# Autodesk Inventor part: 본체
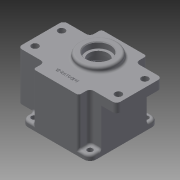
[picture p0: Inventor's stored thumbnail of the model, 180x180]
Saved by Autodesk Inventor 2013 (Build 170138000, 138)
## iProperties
Created: 2015-07
Part Number: 본체
Material: 일반
Document SubType Name: Modeling
Designer: user
Density: 1 g/cm^3
Author: user
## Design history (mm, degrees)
sketch "스케치1"
  geometry: L1 (65, 30)-(65, -30); L2 (-65, -30)-(-65, 30); L3 (-30, 45)-(30, 45); L4 (30, -45)-(-30, -45); L5 (30, 45)-(30, 30); L6 (30, -30)-(30, -45); L7 (-65, 30)-(-30, 30); L8 (30, 30)-(65, 30); L9 (-30, -45)-(-30, -30); L10 (-30, 30)-(-30, 45); L11 (65, -30)-(30, -30); L12 (-30, -30)-(-65, -30); 4 further points
  constraints: 24 end point, 10 parallel, 4 perpendicular, 3 horizontal, 2 horizontal alignment, 2 midpoint, 1 vertical alignment
  dimensions: "d0" = 130 distance of L1.end L2.start; "d1" = 60 distance of L1.start L1.end; "d3" = 60 distance of L4.start L4.end; "d4" = 90 distance of L3.end L4.start
extrude "돌출1" new body sketch "스케치1" distance "d5" = 12; taper "d6" = 0 deg
sketch "스케치2"
  geometry: L1 (-9047.762, 104.614)-(-9047.762, 74.603); L2 (30, 45)-(-30, 45); L3 (-45, 30)-(-45, -30); L4 (-30, -45)-(30, -45); L5 (45, -30)-(45, 30); L6 (30, -45)-(0, -45); L7 (45, 0)-(45, -30); L8 (28.924, 45)-(0, 45); L9 (30, 30)-(65, 30) reference; L10 (65, 30)-(65, -30) reference; L11 (65, -30)-(30, -30) reference; L12 (30, -30)-(30, -45) reference; L13 (30, -45)-(-30, -45) reference; L14 (-30, -45)-(-30, -30) reference; L15 (-30, -30)-(-65, -30) reference; L16 (-65, -30)-(-65, 30) reference; L17 (-65, 30)-(-30, 30) reference; L18 (-30, 30)-(-30, 45) reference; L19 (-30, 45)-(30, 45) reference; L20 (30, 45)-(30, 30) reference; L21 (-30, 45)-(-30, 30); L22 (-30, 30)-(-45, 30); L23 (30, 30)-(45, 30); L24 (30, 45)-(30, 30); L25 (30, -30)-(45, -30); L26 (30, -45)-(30, -30); L27 (-30, -30)-(-45, -30); L28 (-30, -45)-(-30, -30); 1 further point
  constraints: 32 end point, 6 horizontal, 4 parallel, 2 point on line, 1 perpendicular
  dimensions: "d103" = 90 deg angle of L10 L22; "d104" = 90 deg angle of L9 L26; "d105" = 90 deg angle of L9 L21; "d106" = 90 deg angle of L9 L28; "d107" = 20 distance between parallel lines of L10 L5; "d108" = 110 distance between parallel lines of L10 L3; "d109" = 9112.76236 distance between parallel lines of L10 L1; "d110" = 75 distance between parallel lines of L9 L6; "d111" = 15 distance between parallel lines of L9 L2; "d112" = 90 distance between parallel lines of L13 L8; "d113" = 30 distance from line of L7.start L11; "d114" = 36.07569 distance from line of L8.start L10; "d115" = 65 distance from line of L8.end L10; "d116" = 65 distance from line of L6.end L10; "d117" = 134.61417 distance from line of L1.start L11; "d118" = 104.60322 distance from line of L1.end L11
extrude "돌출2" join sketch "스케치2" distance "d14" = 51; taper "d15" = 0 deg
sketch "스케치3"
  geometry: L1 (-45, -45)-(45, -45); L2 (45, -45)-(45, 45); L3 (45, 45)-(-45, 45); L4 (-45, 45)-(-45, -45); 1 further point
  constraints: 8 end point, 2 parallel, 1 horizontal, 1 perpendicular
extrude "돌출3" join sketch "스케치3" distance "d16" = 7; taper "d17" = 0 deg
fillet "모깎기2" dims "d18" = 8
sketch "스케치4"
  geometry: L1 (-37, 45)-(-30, 45) reference; L2 (45, 37)-(45, 30) reference; L3 (37, -45)-(30, -45) reference; L4 (-45, -37)-(-45, -30) reference; L5 (-45, 30)-(-30, 30) reference; L6 (30, 30)-(45, 30) reference; L7 (45, -30)-(30, -30) reference; L8 (-30, -30)-(-45, -30) reference; L9 (-30, -45)-(-37, -45) reference; L10 (30, 45)-(37, 45) reference; L11 (30, 45)-(30, 30) reference; L12 (-30, 45)-(30, 45) reference; L13 (-30, 30)-(-30, 45) reference; L14 (-45, -30)-(-45, 30) reference; L15 (-45, -30)-(-65, -30) reference; L16 (-65, -30)-(-65, 30) reference; L17 (-65, 30)-(-45, 30) reference; L18 (-45, 30)-(-45, 37) reference; L19 (45, 30)-(45, -30) reference; L20 (65, -30)-(45, -30) reference; L21 (65, 30)-(65, -30) reference; L22 (45, 30)-(65, 30) reference; L23 (-30, -45)-(-30, -30) reference; L24 (30, -45)-(-30, -45) reference; L25 (30, -30)-(30, -45) reference; L26 (45, -30)-(45, -37) reference; C1 r 3.5 at (37, 37); C2 r 3.5 at (-37, 37); C3 r 3.5 at (-37, -37); C4 r 3.5 at (37, -37); A1 r 8 centre (-37, 37) between (-37, 45) and (-45, 37) reference; A2 r 8 centre (37, 37) between (45, 37) and (37, 45) reference; A3 r 8 centre (37, -37) between (37, -45) and (45, -37) reference; A4 r 8 centre (-37, -37) between (-45, -37) and (-37, -45) reference; 1 further point
  constraints: 4 centre point, 4 coincident
  dimensions: "d19" = 3.5 radius of C1; "d20" = 3.5 radius of C2; "d21" = 3.5 radius of C3; "d22" = 3.5 radius of C4
extrude "돌출4" cut sketch "스케치4" distance "d23" = 7; taper "d24" = 0 deg
sketch "스케치5"
  geometry: L1 (65, -30)-(65, 30) reference; L2 (-55, 17.5)-(55, 17.5); L3 (55, 17.5)-(55, -17.5); L4 (55, -17.5)-(-55, -17.5); L5 (-55, -17.5)-(-55, 17.5); C1 r 4.5 at (-55, 17.5); C2 r 4.5 at (-55, -17.5); C3 r 4.5 at (55, -17.5); C4 r 4.5 at (55, 17.5); 6 further points
  constraints: 8 end point, 4 centre point, 4 coincident, 3 midpoint, 2 parallel, 1 horizontal, 1 horizontal alignment, 1 perpendicular, 1 vertical alignment
  dimensions: "d25" = 110 distance of L3.end L4.end; "d26" = 35 distance of L2.end L3.end; "d27" = 4.5 radius of C1; "d28" = 4.5 radius of C2; "d29" = 4.5 radius of C3; "d30" = 4.5 radius of C4
extrude "돌출5" cut sketch "스케치5" distance "d31" = 20; taper "d32" = 0 deg
sketch "스케치6"
  geometry: C1 r 40 at (0, 0); 1 further point
  constraints: 1 centre point, 1 coincident
  dimensions: "d33" = 40 radius of C1
extrude "돌출6" cut sketch "스케치6" distance "d34" = 9; taper "d35" = 0 deg
sketch "스케치7"
  geometry: C1 r 40 at (0, 0) reference; C2 r 39 at (0, 0)
  constraints: 1 centre point, 1 coincident
  dimensions: "d36" = 39 radius of C2
extrude "돌출7" cut sketch "스케치7" distance "d38" = 52; taper "d39" = 0 deg
sketch "스케치14"
  geometry: L1 (45, -37)-(45, 37) reference; L2 (0, 0)-(44.326, 0); L3 (0, 0)-(-24.749, 24.749); L4 (0, 0)-(-24.749, -24.749); L5 (0, 0)-(24.749, -24.749); L6 (0, 0)-(24.749, 24.749); A1 r 40 centre (0, 0) between (-21.902, 33.471) and (-33.471, 21.902) reference; A2 r 35 centre (0, 0) between (-24.749, 24.749) and (-21.678, 27.478); A3 r 4 centre (-24.749, 24.749) between (-27.839, 22.208) and (-22.208, 27.839); A4 r 3.5 centre (-19.986, 30.542) between (-21.902, 33.471) and (-21.678, 27.478); A5 r 3.5 centre (-30.542, 19.986) between (-27.478, 21.678) and (-33.471, 21.902)
  constraints: 13 point on circle, 10 end point, 4 centre point, 4 tangent, 2 coincident, 1 horizontal, 13 other
  dimensions: "d56" = 35 radius of A2; "d60" = 360 deg dimension on A1.centre L3.end (derived); "d62" = 4 radius of A3; "d63" = 3.5 radius of A4; "d64" = 3.5 radius of A5; "d65" = 45 deg angle of L1 L6; "d66" = 0.6741 distance from line of L2.end L1
extrude "돌출13" join sketch "스케치14" stored distance "d67" = 10; taper "d68" = 0 deg
sketch "스케치15"
  geometry: L1 (0, 0)-(0, 11); C1 r 20.5 at (0, 11); A1 r 39 centre (0, 0) between (-31.18, 23.427) and (-31.18, -23.427) reference
  constraints: 2 end point, 1 centre point, 1 coincident, 1 vertical
  dimensions: "d72" = 11 distance of L1.start L1.end; "d73" = 20.5 radius of C1
extrude "돌출14" join sketch "스케치15" distance "d74" = 7; taper "d75" = 0 deg
sketch "스케치16"
  geometry: C1 r 20.5 at (0, 0) reference; C2 r 17.5 at (0, 0); 1 further point
  constraints: 1 centre point, 1 coincident
  dimensions: "d76" = 17.5 radius of C2
extrude "돌출15" cut sketch "스케치16" distance "d77" = 10; taper "d78" = 0 deg
sketch "스케치17"
  geometry: L1 (30, 45)-(-30, 45) reference; L2 (0, 0)-(0, 11); C1 r 25 at (0, 11); 2 further points
  constraints: 2 end point, 1 centre point, 1 coincident, 1 perpendicular
  dimensions: "d79" = 11 distance of L2.start L2.end; "d80" = 25 radius of C1
extrude "돌출16" join sketch "스케치17" distance "d81" = 7; taper "d82" = 0 deg
sketch "스케치18"
  geometry: C1 r 25 at (0, 0) reference; C2 r 16 at (0, 0); 1 further point
  constraints: 1 centre point, 1 coincident
  dimensions: "d83" = 16 radius of C2
extrude "돌출17" cut sketch "스케치18" distance "d84" = 8; taper "d85" = 0 deg
sketch "스케치19"
  geometry: C1 r 16 at (0, 0) reference; C2 r 12.5 at (0, 0); 1 further point
  constraints: 1 centre point, 1 coincident
  dimensions: "d86" = 12.5 radius of C2
extrude "돌출18" cut sketch "스케치19" distance "d87" = 5; taper "d88" = 0 deg
sketch "스케치20"
  geometry: C1 r 20.5 at (0, 11) reference; A1 r 3.5 centre (-30.542, -19.986) between (-31.18, -23.427) and (-27.839, -22.208) reference; A2 r 4 centre (-24.749, -24.749) between (-22.208, -27.839) and (-27.839, -22.208) reference; A3 r 3.5 centre (-19.986, -30.542) between (-22.208, -27.839) and (-23.427, -31.18) reference; A4 r 39 centre (0, 0) between (-23.427, -31.18) and (23.427, -31.18) reference; A5 r 3.5 centre (19.986, -30.542) between (23.427, -31.18) and (22.208, -27.839) reference; A6 r 4 centre (24.749, -24.749) between (27.839, -22.208) and (22.208, -27.839) reference; A7 r 3.5 centre (30.542, -19.986) between (27.839, -22.208) and (31.18, -23.427) reference; A8 r 39 centre (0, 0) between (31.18, -23.427) and (31.18, 23.427) reference; A9 r 3.5 centre (30.542, 19.986) between (31.18, 23.427) and (27.839, 22.208) reference; A10 r 4 centre (24.749, 24.749) between (22.208, 27.839) and (27.839, 22.208) reference; A11 r 3.5 centre (19.986, 30.542) between (22.208, 27.839) and (23.427, 31.18) reference; A12 r 39 centre (0, 0) between (23.427, 31.18) and (-23.427, 31.18) reference; A13 r 3.5 centre (-19.986, 30.542) between (-23.427, 31.18) and (-22.208, 27.839) reference; A14 r 4 centre (-24.749, 24.749) between (-27.839, 22.208) and (-22.208, 27.839) reference; A15 r 3.5 centre (-30.542, 19.986) between (-27.839, 22.208) and (-31.18, 23.427) reference; A16 r 39 centre (0, 0) between (-31.18, 23.427) and (-31.18, -23.427) reference
sketch "스케치21"
  geometry: L1 (0, 0)-(0, -20); C1 r 20.5 at (0, 11) reference; A1 r 39 centre (0, 0) between (-31.18, 23.427) and (-31.18, -23.427) reference; A2 r 14 centre (0, -20) between (-7.402, -8.117) and (7.402, -8.117); A3 r 20.5 centre (0, 11) between (-7.402, -8.117) and (7.402, -8.117)
  constraints: 4 point on circle, 2 centre point, 2 coincident, 2 end point, 1 vertical
  dimensions: "d89" = 20 distance of L1.start L1.end; "d90" = 14 radius of A2; "d91" = 20.5 radius of A3
extrude "돌출19" join sketch "스케치21" distance "d92" = 7; taper "d93" = 0 deg
sketch "스케치22"
  geometry: C1 r 11 at (0, -20); A1 r 14 centre (0, -20) between (-7.402, -8.117) and (7.402, -8.117) reference; 1 further point
  constraints: 1 centre point, 1 coincident
  dimensions: "d94" = 11 radius of C1
extrude "돌출20" cut sketch "스케치22" distance "d95" = 7; taper "d96" = 0 deg
sketch "스케치23"
  geometry: C1 r 11 at (0, 0) reference; C2 r 9.5 at (0, 0); 1 further point
  constraints: 1 centre point, 1 coincident
  dimensions: "d97" = 9.5 radius of C2
extrude "돌출21" cut sketch "스케치23" distance "d98" = 1; taper "d99" = 0 deg
fillet "모깎기3" dims "d119" = 5
fillet "모깎기4" dims "d120" = 3
sketch "스케치24"
  geometry: L1 (-27, -45)-(27, -45) reference; L2 (0, -45)-(0, -30); 2 further points
  constraints: 2 end point, 1 midpoint, 1 perpendicular, 1 other
  dimensions: "d121" = 15 distance of L2.start L2.end
extrude "돌출22" join sketch "스케치24" distance "d122" = 0.5; taper "d123" = 0 deg
fillet "모깎기5" dims "d124" = 3
fillet "모깎기6" dims "d125" = 3
fillet "모깎기7" dims "d126" = 3
chamfer "모따기1" distance "d127" = 1; stored, may be unused: second distance "d128" = 2, angle "d129" = 45 deg
chamfer "모따기2" distance "d130" = 1; stored, may be unused: second distance "d131" = 2, angle "d132" = 45 deg
sketch "스케치25"
  geometry: A1 r 4 centre (-24.749, 24.749) between (-27.839, 22.208) and (-22.208, 27.839) reference
hole "구멍1" sketch "스케치25" at (-24.749, 24.749) diameter "d133" = 3.459; stored, may be unused: countersink angle "d137" = 90 deg, drill point angle "d139" = 118 deg; dims "d134" = 12, "d135" = 4, "d136" = 2, "d138" = 15
fillet "모깎기8" dims "d143" = 0.3
fillet "모깎기9" dims "d144" = 0.3
fillet "모깎기10" dims "d145" = 3
sketch "스케치26"
  geometry: L1 (-60, -30)-(-47.196, -30) reference; L2 (-45, 30.569)-(-45, -30.569) reference; L3 (-47.196, 30)-(-60, 30) reference; L4 (-65, 25)-(-65, -25) reference; L5 (-65, 25)-(-65, -25); L6 (-60, -30)-(-47.196, -30); L7 (-60, 30)-(-47.196, 30); L8 (-45, 30.569)-(-45, -30.569); L9 (-45, -30.569)-(-47.196, -32.23); L10 (-47.196, -32.23)-(-47.196, -30); L11 (-47.196, 30)-(-47.196, 32.518); C1 r 5 at (-60, 25); A1 r 5 centre (-60, -25) between (-65, -25) and (-60, -30) reference; A2 r 5 centre (-60, 25) between (-60, 30) and (-65, 25) reference; 2 further points
  constraints: 14 end point, 6 tangent, 5 collinear, 2 coincident, 1 centre point, 1 horizontal, 1 parallel, 1 vertical, 1 vertical alignment, 4 other
extrude "돌출23" cut sketch "스케치26" distance "d146" = 51; taper "d147" = 0 deg
node "솔리드1"
pattern_circular "원형 패턴1" dims angle "d70" = 360 deg
pattern_circular "원형 패턴2" dims angle "d141" = 360 deg
node "절단 모서리 투영1"
node "절단 모서리 투영2"
other parameters: "d57" = 135 deg
